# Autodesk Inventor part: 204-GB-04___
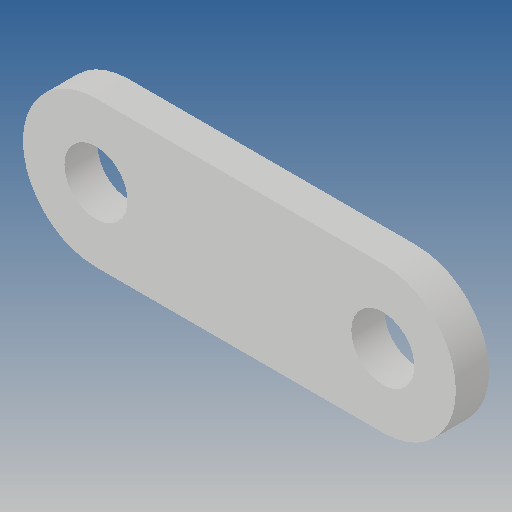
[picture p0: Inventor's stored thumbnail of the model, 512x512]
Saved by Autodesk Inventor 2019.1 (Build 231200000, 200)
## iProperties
Created: 2012-09
Part Number: 204-GB-04___
Material: Ogólny
Document SubType Name: Modeling
Designer: CADENGINEERING4
Density: 1 g/cm^3
Appearance: Domyślna
Author: CADENGINEERING4
Revision Number: ÈÎºÎ
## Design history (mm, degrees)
feature "NONE"
node "Bryła1"
